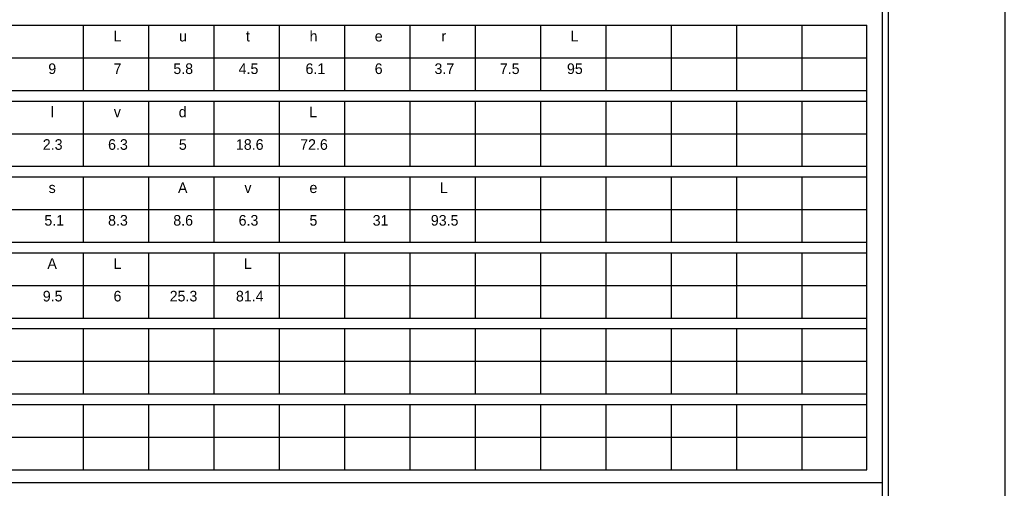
# Model space of a CAD drawing. Extents: x 1274.1 to 1363.1, y 833.5 to 890.6.
# Drawn here: x 1338.12 to 1363.1, y 864.07 to 875.95 of the extents above; entities that cross this region are included whole.
import ezdxf

# ---------------------------------------------------------------- set-up
doc = ezdxf.new("R2010")
doc.units = 0
for name, color, linetype in [('GSSign', 7, 'Continuous'), ('PlotBorder_dp', 7, 'Continuous'), ('SheetBorder_dp', 7, 'Continuous'), ('SheetLinesMisc2_dp', 7, 'Continuous')]:
    doc.layers.add(name, color=color, linetype=linetype)

msp = doc.modelspace()

# ---------------------------------------------------------------- linework, layer by layer
at = {"layer": 'PlotBorder_dp'}
msp.add_lwpolyline([(1274.135, 833.481), (1363.097, 833.481), (1363.097, 890.634), (1274.135, 890.634)], close=True, dxfattribs=at)
at = {"layer": 'SheetBorder_dp'}
msp.add_line((1360.132, 890.095), (1360.132, 834.02), dxfattribs=at)
at = {"layer": 'SheetLinesMisc2_dp'}
for p, q in [((1359.988, 838.462), (1359.988, 889.967)), ((1318.9, 875.806), (1359.592, 875.806)), ((1339.728, 875.806), (1339.728, 874.153)), ((1341.384, 875.806), (1341.384, 874.153)), ((1343.039, 875.806), (1343.039, 874.153)), ((1344.694, 875.806), (1344.694, 874.153)), ((1346.349, 875.806), (1346.349, 874.153)), ((1348.005, 875.806), (1348.005, 874.153)), ((1349.66, 875.806), (1349.66, 874.153)), ((1351.315, 875.806), (1351.315, 874.153)), ((1352.971, 875.806), (1352.971, 874.153)), ((1354.626, 875.806), (1354.626, 874.153)), ((1356.282, 875.806), (1356.282, 874.153)), ((1357.937, 875.806), (1357.937, 874.153)), ((1359.592, 864.539), (1359.592, 875.806)), ((1318.9, 874.979), (1359.592, 874.979)), ((1318.9, 874.153), (1359.592, 874.153)), ((1318.9, 873.883), (1359.592, 873.883)), ((1339.728, 873.883), (1339.728, 872.23)), ((1341.384, 873.883), (1341.384, 872.23)), ((1343.039, 873.883), (1343.039, 872.23)), ((1344.694, 873.883), (1344.694, 872.23)), ((1346.349, 873.883), (1346.349, 872.23)), ((1348.005, 873.883), (1348.005, 872.23)), ((1349.66, 873.883), (1349.66, 872.23)), ((1351.315, 873.883), (1351.315, 872.23)), ((1352.971, 873.883), (1352.971, 872.23)), ((1354.626, 873.883), (1354.626, 872.23)), ((1356.282, 873.883), (1356.282, 872.23)), ((1357.937, 873.883), (1357.937, 872.23)), ((1318.9, 873.056), (1359.592, 873.057)), ((1318.9, 872.23), (1359.592, 872.23)), ((1318.9, 871.96), (1359.592, 871.96)), ((1339.728, 871.96), (1339.728, 870.307)), ((1341.384, 871.96), (1341.384, 870.307)), ((1343.039, 871.96), (1343.039, 870.307)), ((1344.694, 871.96), (1344.694, 870.307)), ((1346.349, 871.96), (1346.349, 870.307)), ((1348.005, 871.96), (1348.005, 870.307)), ((1349.66, 871.96), (1349.66, 870.307)), ((1351.315, 871.96), (1351.315, 870.307)), ((1352.971, 871.96), (1352.971, 870.307)), ((1354.626, 871.96), (1354.626, 870.307)), ((1356.282, 871.96), (1356.282, 870.307)), ((1357.937, 871.96), (1357.937, 870.307)), ((1318.9, 871.134), (1359.592, 871.134)), ((1318.9, 870.307), (1359.592, 870.307)), ((1318.9, 870.038), (1359.592, 870.038)), ((1339.728, 870.038), (1339.728, 868.384)), ((1341.384, 870.038), (1341.384, 868.384)), ((1343.039, 870.038), (1343.039, 868.384)), ((1344.694, 870.038), (1344.694, 868.384)), ((1346.349, 870.038), (1346.349, 868.384)), ((1348.005, 870.038), (1348.005, 868.384)), ((1349.66, 870.038), (1349.66, 868.384)), ((1351.315, 870.038), (1351.315, 868.384)), ((1352.971, 870.038), (1352.971, 868.384)), ((1354.626, 870.038), (1354.626, 868.384)), ((1356.282, 870.038), (1356.282, 868.384)), ((1357.937, 870.038), (1357.937, 868.384)), ((1318.9, 869.211), (1359.592, 869.211)), ((1318.9, 868.384), (1359.592, 868.384)), ((1318.9, 868.115), (1359.592, 868.115)), ((1339.728, 868.115), (1339.728, 866.462)), ((1341.384, 868.115), (1341.384, 866.462)), ((1343.039, 868.115), (1343.039, 866.462)), ((1344.694, 868.115), (1344.694, 866.462)), ((1346.349, 868.115), (1346.349, 866.462)), ((1348.005, 868.115), (1348.005, 866.462)), ((1349.66, 868.115), (1349.66, 866.462)), ((1351.315, 868.115), (1351.315, 866.462)), ((1352.971, 868.115), (1352.971, 866.462)), ((1354.626, 868.115), (1354.626, 866.462)), ((1356.282, 868.115), (1356.282, 866.462)), ((1357.937, 868.115), (1357.937, 866.462)), ((1318.9, 867.288), (1359.592, 867.288)), ((1318.9, 866.462), (1359.592, 866.462)), ((1318.9, 866.192), (1359.592, 866.192)), ((1339.728, 866.192), (1339.728, 864.539)), ((1341.384, 866.192), (1341.384, 864.539)), ((1343.039, 866.192), (1343.039, 864.539)), ((1344.694, 866.192), (1344.694, 864.539)), ((1346.349, 866.192), (1346.349, 864.539)), ((1348.005, 866.192), (1348.005, 864.539)), ((1349.66, 866.192), (1349.66, 864.539)), ((1351.315, 866.192), (1351.315, 864.539)), ((1352.971, 866.192), (1352.971, 864.539)), ((1354.626, 866.192), (1354.626, 864.539)), ((1356.282, 866.192), (1356.282, 864.539)), ((1357.937, 866.192), (1357.937, 864.539)), ((1318.9, 865.366), (1359.592, 865.366)), ((1318.9, 864.539), (1359.592, 864.539)), ((1277.247, 864.214), (1359.988, 864.214))]:
    msp.add_line(p, q, dxfattribs=at)

# ---------------------------------------------------------------- texts
at = {"layer": 'GSSign'}
for s, height, p in [('L', 0.269, (1340.492, 875.396)), ('u', 0.269, (1342.154, 875.396)), ('t', 0.269, (1343.849, 875.396)), ('h', 0.269, (1345.463, 875.396)), ('e', 0.269, (1347.116, 875.396)), ('r', 0.269, (1348.805, 875.396)), ('L', 0.269, (1352.076, 875.396)), ('9', 0.269, (1338.841, 874.57)), ('7', 0.269, (1340.495, 874.57)), ('5.8', 0.2694, (1342.01, 874.57)), ('4.5', 0.2694, (1343.665, 874.57)), ('6.1', 0.2694, (1345.361, 874.57)), ('6', 0.269, (1347.114, 874.57)), ('3.7', 0.2694, (1348.629, 874.57)), ('7.5', 0.2694, (1350.285, 874.57)), ('95', 0.2694, (1351.987, 874.57)), ('l', 0.269, (1338.904, 873.474)), ('v', 0.269, (1340.501, 873.474)), ('d', 0.269, (1342.147, 873.474)), ('L', 0.269, (1345.456, 873.474)), ('2.3', 0.2694, (1338.701, 872.648)), ('6.3', 0.2694, (1340.356, 872.648)), ('5', 0.269, (1342.151, 872.648)), ('18.6', 0.2694, (1343.596, 872.648)), ('72.6', 0.2694, (1345.225, 872.648)), ('s', 0.269, (1338.849, 871.553)), ('A', 0.269, (1342.128, 871.553)), ('v', 0.269, (1343.811, 871.553)), ('e', 0.269, (1345.461, 871.553)), ('L', 0.269, (1348.766, 871.553)), ('5.1', 0.2694, (1338.741, 870.726)), ('8.3', 0.2694, (1340.356, 870.726)), ('8.6', 0.2694, (1342.009, 870.726)), ('6.3', 0.2694, (1343.665, 870.726)), ('5', 0.269, (1345.461, 870.726)), ('31', 0.2694, (1347.062, 870.726)), ('93.5', 0.2694, (1348.536, 870.726)), ('A', 0.269, (1338.818, 869.631)), ('L', 0.269, (1340.492, 869.631)), ('L', 0.269, (1343.801, 869.631)), ('9.5', 0.2694, (1338.701, 868.804)), ('6', 0.269, (1340.495, 868.804)), ('25.3', 0.2694, (1341.917, 868.804)), ('81.4', 0.2694, (1343.596, 868.804))]:
    msp.add_text(s, height=height, dxfattribs=at).set_placement(p)

doc.saveas('drawing.dxf')
